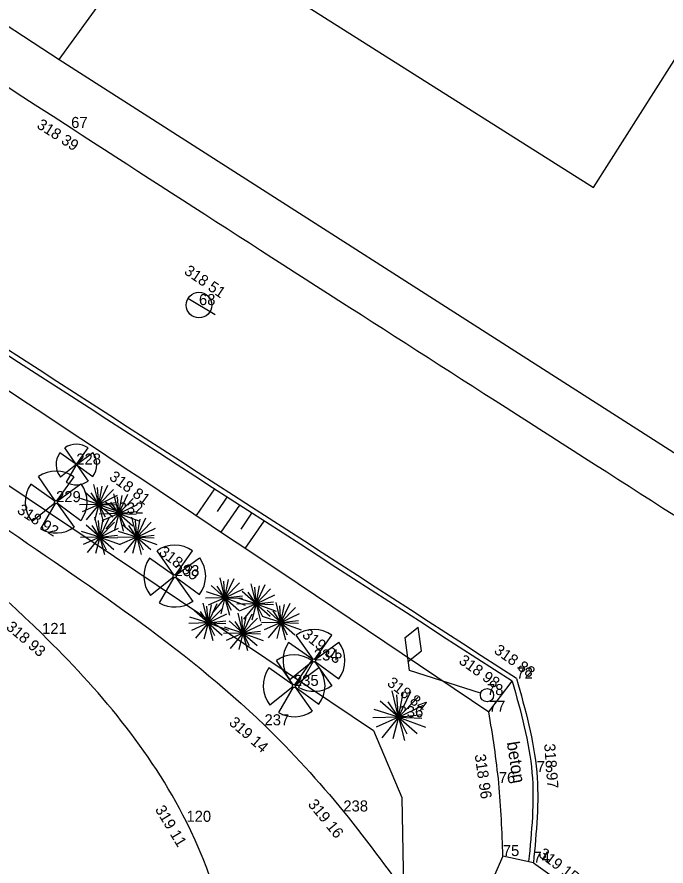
# Model space of a CAD drawing. Extents: x -742884 to -742543, y -1054677 to -1054433.
# Drawn here: x -742681.87 to -742664.25, y -1054523.59 to -1054500.54 of the extents above; entities that cross this region are included whole.
import ezdxf

# ---------------------------------------------------------------- set-up
doc = ezdxf.new("R2010")
doc.units = 0
for name, color, linetype in [('Vrstva 1', 7, 'Continuous'), ('Vrstva 10', 7, 'Continuous'), ('Vrstva 11', 7, 'Continuous'), ('Vrstva 12', 7, 'Continuous'), ('Vrstva 13', 7, 'Continuous'), ('Vrstva 15', 7, 'Continuous'), ('Vrstva 2', 7, 'Continuous'), ('Vrstva 3', 7, 'Continuous'), ('Vrstva 4', 7, 'Continuous'), ('Vrstva 50', 7, 'Continuous'), ('Vrstva 7', 7, 'Continuous')]:
    doc.layers.add(name, color=color, linetype=linetype)

# ---------------------------------------------------------------- blocks, each defined once
blk = doc.blocks.new('Z15')
at = {"layer": 'Vrstva 2'}
for p, q in [((-10, 2), (-8, 6)), ((-10, -2), (-10, 2)), ((-8, 6), (-6, 8)), ((-6, 8), (-2, 10)), ((-2, 10), (2, 10)), ((2, 10), (6, 8)), ((6, 8), (8, 6)), ((8, 6), (10, 2)), ((10, 2), (10, -2)), ((-8, -6), (-10, -2)), ((-6, -8), (-8, -6)), ((-2, -10), (-6, -8)), ((2, -10), (-2, -10)), ((6, -8), (2, -10)), ((8, -6), (6, -8)), ((10, -2), (8, -6))]:
    blk.add_line(p, q, dxfattribs=at)

msp = doc.modelspace()

# ---------------------------------------------------------------- linework, layer by layer
at = {"layer": 'Vrstva 1'}
for p, q in [((-742680.4, -1054503.55), (-742680.4, -1054503.55)), ((-742676.93, -1054508.36), (-742676.93, -1054508.36)), ((-742680.26, -1054512.69), (-742680.26, -1054512.69)), ((-742680.81, -1054513.71), (-742680.81, -1054513.71)), ((-742679.11, -1054514.02), (-742679.11, -1054514.02)), ((-742677.59, -1054515.72), (-742677.59, -1054515.72)), ((-742681.19, -1054517.29), (-742681.19, -1054517.29)), ((-742673.81, -1054518.01), (-742673.81, -1054518.01)), ((-742668.31, -1054518.5), (-742668.31, -1054518.5)), ((-742674.35, -1054518.7), (-742674.35, -1054518.7)), ((-742669.11, -1054518.95), (-742669.11, -1054518.95)), ((-742669.06, -1054519.4), (-742669.06, -1054519.4)), ((-742671.51, -1054519.55), (-742671.51, -1054519.55)), ((-742675.15, -1054519.77), (-742675.15, -1054519.77)), ((-742667.76, -1054521.04), (-742667.76, -1054521.04)), ((-742668.79, -1054521.34), (-742668.79, -1054521.34)), ((-742673.01, -1054522.11), (-742673.01, -1054522.11)), ((-742677.27, -1054522.39), (-742677.27, -1054522.39)), ((-742668.68, -1054523.32), (-742668.68, -1054523.32)), ((-742667.85, -1054523.5), (-742667.85, -1054523.5))]:
    msp.add_line(p, q, dxfattribs=at)
at = {"layer": 'Vrstva 10'}
for p, q in [((-742680.273, -1054512.669), (-742680.573, -1054512.237)), ((-742680.244, -1054512.669), (-742679.94, -1054512.239)), ((-742680.282, -1054512.672), (-742680.708, -1054512.37)), ((-742680.238, -1054512.676), (-742679.815, -1054512.361)), ((-742680.282, -1054512.709), (-742680.687, -1054513.035)), ((-742680.276, -1054512.715), (-742680.536, -1054513.165)), ((-742680.24, -1054512.713), (-742679.939, -1054513.139)), ((-742680.236, -1054512.706), (-742679.815, -1054513.017)), ((-742680.83, -1054513.677), (-742681.287, -1054513.018)), ((-742680.785, -1054513.677), (-742680.322, -1054513.024)), ((-742680.778, -1054513.686), (-742680.134, -1054513.209)), ((-742680.843, -1054513.682), (-742681.495, -1054513.223)), ((-742679.65, -1054513.77), (-742680.025, -1054513.441)), ((-742679.65, -1054513.77), (-742679.783, -1054513.231)), ((-742679.65, -1054513.77), (-742679.684, -1054513.316)), ((-742679.65, -1054513.77), (-742679.402, -1054513.245)), ((-742679.65, -1054513.77), (-742679.557, -1054513.279)), ((-742679.65, -1054513.77), (-742679.254, -1054513.365)), ((-742679.65, -1054513.77), (-742680.149, -1054513.613)), ((-742679.65, -1054513.77), (-742679.861, -1054513.458)), ((-742679.65, -1054513.77), (-742679.142, -1054513.525)), ((-742679.11, -1054514.02), (-742679.243, -1054513.481)), ((-742679.11, -1054514.02), (-742679.144, -1054513.566)), ((-742679.11, -1054514.02), (-742678.862, -1054513.495)), ((-742679.11, -1054514.02), (-742679.017, -1054513.529)), ((-742679.11, -1054514.02), (-742678.714, -1054513.615)), ((-742680.844, -1054513.739), (-742681.463, -1054514.236)), ((-742680.835, -1054513.747), (-742681.232, -1054514.435)), ((-742680.782, -1054513.744), (-742680.321, -1054514.394)), ((-742680.774, -1054513.735), (-742680.134, -1054514.208)), ((-742679.65, -1054513.77), (-742680.176, -1054513.784)), ((-742679.65, -1054513.77), (-742680.105, -1054513.972)), ((-742679.65, -1054513.77), (-742679.995, -1054514.188)), ((-742679.65, -1054513.77), (-742679.765, -1054514.211)), ((-742679.654, -1054513.768), (-742679.654, -1054513.768)), ((-742679.65, -1054513.77), (-742679.173, -1054513.717)), ((-742679.65, -1054513.77), (-742679.65, -1054513.77)), ((-742679.65, -1054513.77), (-742679.479, -1054514.111)), ((-742679.65, -1054513.77), (-742679.1, -1054513.97)), ((-742679.65, -1054513.77), (-742679.173, -1054513.786)), ((-742679.65, -1054513.77), (-742679.269, -1054514.105)), ((-742679.65, -1054513.77), (-742679.528, -1054514.244)), ((-742679.65, -1054513.77), (-742679.65, -1054513.77)), ((-742679.11, -1054514.02), (-742679.609, -1054513.863)), ((-742679.11, -1054514.02), (-742679.485, -1054513.691)), ((-742679.11, -1054514.02), (-742679.321, -1054513.708)), ((-742679.11, -1054514.02), (-742678.602, -1054513.775)), ((-742679.62, -1054514.66), (-742679.753, -1054514.121)), ((-742679.11, -1054514.02), (-742679.636, -1054514.034)), ((-742679.62, -1054514.66), (-742679.372, -1054514.135)), ((-742679.11, -1054514.02), (-742679.565, -1054514.222)), ((-742679.11, -1054514.02), (-742679.455, -1054514.438)), ((-742679.11, -1054514.02), (-742679.225, -1054514.461)), ((-742679.114, -1054514.018), (-742679.114, -1054514.018)), ((-742679.11, -1054514.02), (-742678.633, -1054513.967)), ((-742679.11, -1054514.02), (-742679.11, -1054514.02)), ((-742679.11, -1054514.02), (-742678.939, -1054514.361)), ((-742679.11, -1054514.02), (-742678.56, -1054514.22)), ((-742679.11, -1054514.02), (-742678.633, -1054514.036)), ((-742679.11, -1054514.02), (-742678.729, -1054514.355)), ((-742679.11, -1054514.02), (-742678.988, -1054514.494)), ((-742679.11, -1054514.02), (-742679.11, -1054514.02)), ((-742678.62, -1054514.66), (-742678.753, -1054514.121)), ((-742678.62, -1054514.66), (-742678.372, -1054514.135)), ((-742679.62, -1054514.66), (-742679.995, -1054514.331)), ((-742679.62, -1054514.66), (-742679.831, -1054514.348)), ((-742679.62, -1054514.66), (-742679.654, -1054514.206)), ((-742679.62, -1054514.66), (-742679.527, -1054514.169)), ((-742679.62, -1054514.66), (-742679.224, -1054514.255)), ((-742678.62, -1054514.66), (-742678.995, -1054514.331)), ((-742678.62, -1054514.66), (-742678.831, -1054514.348)), ((-742678.62, -1054514.66), (-742678.654, -1054514.206)), ((-742678.62, -1054514.66), (-742678.527, -1054514.169)), ((-742678.62, -1054514.66), (-742678.224, -1054514.255)), ((-742679.62, -1054514.66), (-742680.119, -1054514.503)), ((-742679.62, -1054514.66), (-742679.112, -1054514.415)), ((-742678.62, -1054514.66), (-742679.119, -1054514.503)), ((-742678.62, -1054514.66), (-742678.112, -1054514.415)), ((-742679.62, -1054514.66), (-742680.146, -1054514.674)), ((-742679.62, -1054514.66), (-742680.075, -1054514.862)), ((-742679.62, -1054514.66), (-742679.965, -1054515.078)), ((-742679.62, -1054514.66), (-742679.735, -1054515.101)), ((-742679.624, -1054514.658), (-742679.624, -1054514.658)), ((-742679.62, -1054514.66), (-742679.143, -1054514.607)), ((-742679.62, -1054514.66), (-742679.62, -1054514.66)), ((-742679.62, -1054514.66), (-742679.449, -1054515.001)), ((-742679.62, -1054514.66), (-742679.07, -1054514.86)), ((-742679.62, -1054514.66), (-742679.143, -1054514.676)), ((-742679.62, -1054514.66), (-742679.239, -1054514.995)), ((-742679.62, -1054514.66), (-742679.498, -1054515.134)), ((-742679.62, -1054514.66), (-742679.62, -1054514.66)), ((-742678.62, -1054514.66), (-742679.146, -1054514.674)), ((-742678.62, -1054514.66), (-742679.075, -1054514.862)), ((-742678.62, -1054514.66), (-742678.965, -1054515.078)), ((-742678.62, -1054514.66), (-742678.735, -1054515.101)), ((-742678.624, -1054514.658), (-742678.624, -1054514.658)), ((-742678.62, -1054514.66), (-742678.143, -1054514.607)), ((-742678.62, -1054514.66), (-742678.62, -1054514.66)), ((-742678.62, -1054514.66), (-742678.449, -1054515.001)), ((-742678.62, -1054514.66), (-742678.07, -1054514.86)), ((-742678.62, -1054514.66), (-742678.143, -1054514.676)), ((-742678.62, -1054514.66), (-742678.239, -1054514.995)), ((-742678.62, -1054514.66), (-742678.498, -1054515.134)), ((-742678.62, -1054514.66), (-742678.62, -1054514.66)), ((-742677.61, -1054515.687), (-742678.067, -1054515.028)), ((-742677.565, -1054515.687), (-742677.102, -1054515.034)), ((-742677.623, -1054515.692), (-742678.275, -1054515.233)), ((-742677.558, -1054515.696), (-742676.914, -1054515.219)), ((-742677.624, -1054515.749), (-742678.243, -1054516.246)), ((-742677.554, -1054515.745), (-742676.914, -1054516.218)), ((-742677.615, -1054515.757), (-742678.012, -1054516.445)), ((-742677.562, -1054515.754), (-742677.101, -1054516.404)), ((-742676.225, -1054516.306), (-742676.6, -1054515.977)), ((-742676.225, -1054516.306), (-742676.358, -1054515.767)), ((-742676.225, -1054516.306), (-742676.259, -1054515.852)), ((-742676.225, -1054516.306), (-742675.977, -1054515.781)), ((-742676.225, -1054516.306), (-742676.132, -1054515.815)), ((-742676.225, -1054516.306), (-742675.829, -1054515.901)), ((-742675.38, -1054516.47), (-742675.513, -1054515.931)), ((-742675.38, -1054516.47), (-742675.132, -1054515.945)), ((-742675.38, -1054516.47), (-742675.287, -1054515.979)), ((-742676.225, -1054516.306), (-742676.724, -1054516.149)), ((-742676.225, -1054516.306), (-742676.436, -1054515.994)), ((-742676.225, -1054516.306), (-742675.717, -1054516.061)), ((-742675.38, -1054516.47), (-742675.755, -1054516.141)), ((-742675.38, -1054516.47), (-742675.591, -1054516.158)), ((-742675.38, -1054516.47), (-742675.414, -1054516.016)), ((-742675.38, -1054516.47), (-742674.984, -1054516.065)), ((-742676.225, -1054516.306), (-742676.751, -1054516.32)), ((-742676.225, -1054516.306), (-742676.68, -1054516.508)), ((-742676.225, -1054516.306), (-742676.57, -1054516.724)), ((-742676.225, -1054516.306), (-742676.34, -1054516.747)), ((-742676.229, -1054516.304), (-742676.229, -1054516.304)), ((-742676.225, -1054516.306), (-742675.748, -1054516.253)), ((-742676.225, -1054516.306), (-742676.225, -1054516.306)), ((-742676.225, -1054516.306), (-742676.054, -1054516.647)), ((-742676.225, -1054516.306), (-742675.675, -1054516.506)), ((-742676.225, -1054516.306), (-742675.748, -1054516.322)), ((-742676.225, -1054516.306), (-742675.844, -1054516.641)), ((-742676.225, -1054516.306), (-742676.103, -1054516.78)), ((-742676.225, -1054516.306), (-742676.225, -1054516.306)), ((-742675.38, -1054516.47), (-742675.879, -1054516.313)), ((-742675.38, -1054516.47), (-742674.872, -1054516.225)), ((-742675.38, -1054516.47), (-742674.903, -1054516.417)), ((-742674.705, -1054516.976), (-742674.838, -1054516.437)), ((-742676.68, -1054516.99), (-742677.055, -1054516.661)), ((-742676.68, -1054516.99), (-742676.813, -1054516.451)), ((-742676.68, -1054516.99), (-742676.714, -1054516.536)), ((-742676.68, -1054516.99), (-742676.432, -1054516.465)), ((-742676.68, -1054516.99), (-742676.587, -1054516.499)), ((-742676.68, -1054516.99), (-742676.284, -1054516.585)), ((-742675.38, -1054516.47), (-742675.906, -1054516.484)), ((-742675.38, -1054516.47), (-742675.835, -1054516.672)), ((-742675.38, -1054516.47), (-742675.725, -1054516.888)), ((-742675.38, -1054516.47), (-742675.495, -1054516.911)), ((-742675.384, -1054516.468), (-742675.384, -1054516.468)), ((-742675.38, -1054516.47), (-742675.38, -1054516.47)), ((-742675.38, -1054516.47), (-742675.209, -1054516.811)), ((-742675.38, -1054516.47), (-742674.83, -1054516.67)), ((-742675.38, -1054516.47), (-742674.903, -1054516.486)), ((-742675.38, -1054516.47), (-742674.999, -1054516.805)), ((-742675.38, -1054516.47), (-742675.258, -1054516.944)), ((-742675.38, -1054516.47), (-742675.38, -1054516.47)), ((-742674.705, -1054516.976), (-742675.08, -1054516.647)), ((-742674.705, -1054516.976), (-742674.916, -1054516.664)), ((-742674.705, -1054516.976), (-742674.739, -1054516.522)), ((-742674.705, -1054516.976), (-742674.457, -1054516.451)), ((-742674.705, -1054516.976), (-742674.612, -1054516.485)), ((-742674.705, -1054516.976), (-742674.309, -1054516.571)), ((-742676.68, -1054516.99), (-742677.179, -1054516.833)), ((-742676.68, -1054516.99), (-742676.891, -1054516.678)), ((-742676.68, -1054516.99), (-742676.172, -1054516.745)), ((-742675.735, -1054517.266), (-742675.868, -1054516.727)), ((-742675.735, -1054517.266), (-742675.769, -1054516.812)), ((-742675.735, -1054517.266), (-742675.487, -1054516.741)), ((-742675.735, -1054517.266), (-742675.642, -1054516.775)), ((-742675.735, -1054517.266), (-742675.339, -1054516.861)), ((-742674.705, -1054516.976), (-742675.204, -1054516.819)), ((-742674.705, -1054516.976), (-742674.197, -1054516.731)), ((-742676.68, -1054516.99), (-742677.206, -1054517.004)), ((-742676.68, -1054516.99), (-742677.135, -1054517.192)), ((-742676.68, -1054516.99), (-742677.025, -1054517.408)), ((-742676.68, -1054516.99), (-742676.795, -1054517.431)), ((-742676.684, -1054516.988), (-742676.684, -1054516.988)), ((-742676.68, -1054516.99), (-742676.203, -1054516.937)), ((-742676.68, -1054516.99), (-742676.68, -1054516.99)), ((-742676.68, -1054516.99), (-742676.509, -1054517.331)), ((-742676.68, -1054516.99), (-742676.13, -1054517.19)), ((-742676.68, -1054516.99), (-742676.203, -1054517.006)), ((-742676.68, -1054516.99), (-742676.299, -1054517.325)), ((-742676.68, -1054516.99), (-742676.558, -1054517.464)), ((-742676.68, -1054516.99), (-742676.68, -1054516.99)), ((-742675.735, -1054517.266), (-742676.234, -1054517.109)), ((-742675.735, -1054517.266), (-742676.11, -1054516.937)), ((-742675.735, -1054517.266), (-742675.946, -1054516.954)), ((-742675.735, -1054517.266), (-742675.227, -1054517.021)), ((-742674.705, -1054516.976), (-742675.231, -1054516.99)), ((-742674.705, -1054516.976), (-742675.16, -1054517.178)), ((-742674.705, -1054516.976), (-742675.05, -1054517.394)), ((-742674.705, -1054516.976), (-742674.82, -1054517.417)), ((-742674.709, -1054516.974), (-742674.709, -1054516.974)), ((-742674.705, -1054516.976), (-742674.228, -1054516.923)), ((-742674.705, -1054516.976), (-742674.705, -1054516.976)), ((-742674.705, -1054516.976), (-742674.534, -1054517.317)), ((-742674.705, -1054516.976), (-742674.155, -1054517.176)), ((-742674.705, -1054516.976), (-742674.228, -1054516.992)), ((-742674.705, -1054516.976), (-742674.324, -1054517.311)), ((-742674.705, -1054516.976), (-742674.583, -1054517.45)), ((-742674.705, -1054516.976), (-742674.705, -1054516.976)), ((-742675.735, -1054517.266), (-742676.261, -1054517.28)), ((-742675.735, -1054517.266), (-742676.19, -1054517.468)), ((-742675.735, -1054517.266), (-742676.08, -1054517.684)), ((-742675.735, -1054517.266), (-742675.85, -1054517.707)), ((-742675.739, -1054517.264), (-742675.739, -1054517.264)), ((-742675.735, -1054517.266), (-742675.258, -1054517.213)), ((-742675.735, -1054517.266), (-742675.735, -1054517.266)), ((-742675.735, -1054517.266), (-742675.564, -1054517.607)), ((-742675.735, -1054517.266), (-742675.185, -1054517.466)), ((-742675.735, -1054517.266), (-742675.258, -1054517.282)), ((-742675.735, -1054517.266), (-742675.354, -1054517.601)), ((-742675.735, -1054517.266), (-742675.613, -1054517.74)), ((-742675.735, -1054517.266), (-742675.735, -1054517.266)), ((-742673.83, -1054517.977), (-742674.287, -1054517.318)), ((-742673.785, -1054517.977), (-742673.322, -1054517.324)), ((-742673.843, -1054517.982), (-742674.495, -1054517.523)), ((-742673.778, -1054517.986), (-742673.134, -1054517.509)), ((-742674.37, -1054518.667), (-742674.827, -1054518.008)), ((-742673.844, -1054518.039), (-742674.463, -1054518.536)), ((-742674.325, -1054518.667), (-742673.862, -1054518.014)), ((-742673.835, -1054518.047), (-742674.232, -1054518.735)), ((-742673.782, -1054518.044), (-742673.321, -1054518.694)), ((-742673.774, -1054518.035), (-742673.134, -1054518.508)), ((-742674.383, -1054518.672), (-742675.035, -1054518.213)), ((-742674.318, -1054518.676), (-742673.674, -1054518.199)), ((-742674.384, -1054518.729), (-742675.003, -1054519.226)), ((-742674.375, -1054518.737), (-742674.772, -1054519.425)), ((-742674.322, -1054518.734), (-742673.861, -1054519.384)), ((-742674.314, -1054518.725), (-742673.674, -1054519.198)), ((-742671.51, -1054519.55), (-742671.687, -1054518.833)), ((-742671.51, -1054519.55), (-742671.555, -1054518.946)), ((-742671.51, -1054519.55), (-742671.18, -1054518.85)), ((-742671.51, -1054519.55), (-742671.387, -1054518.896)), ((-742671.51, -1054519.55), (-742672.011, -1054519.112)), ((-742671.51, -1054519.55), (-742671.792, -1054519.135)), ((-742671.51, -1054519.55), (-742670.983, -1054519.01)), ((-742671.51, -1054519.55), (-742672.175, -1054519.341)), ((-742671.51, -1054519.55), (-742670.834, -1054519.223)), ((-742671.51, -1054519.55), (-742672.211, -1054519.569)), ((-742671.51, -1054519.55), (-742672.116, -1054519.818)), ((-742671.51, -1054519.55), (-742671.969, -1054520.106)), ((-742671.51, -1054519.55), (-742671.664, -1054520.136)), ((-742671.516, -1054519.548), (-742671.516, -1054519.548)), ((-742671.514, -1054519.548), (-742671.514, -1054519.548)), ((-742671.51, -1054519.55), (-742670.875, -1054519.48)), ((-742671.51, -1054519.55), (-742671.51, -1054519.55)), ((-742671.51, -1054519.55), (-742671.51, -1054519.55)), ((-742671.51, -1054519.55), (-742671.51, -1054519.55)), ((-742671.51, -1054519.55), (-742671.284, -1054520.004)), ((-742671.51, -1054519.55), (-742670.779, -1054519.816)), ((-742671.51, -1054519.55), (-742670.875, -1054519.572)), ((-742671.51, -1054519.55), (-742671.003, -1054519.995)), ((-742671.51, -1054519.55), (-742671.349, -1054520.18)), ((-742671.51, -1054519.55), (-742671.51, -1054519.55))]:
    msp.add_line(p, q, dxfattribs=at)
for centre, radius, start, end in [((-742680.258, -1054512.689), 0.551, 54.7465, 124.8105), ((-742680.259, -1054512.687), 0.551, 144.8767, 218.9336), ((-742680.258, -1054512.689), 0.551, 323.4756, 36.2971), ((-742680.808, -1054513.708), 0.84, 54.7465, 124.8105), ((-742680.258, -1054512.689), 0.551, 239.6151, 305.4552), ((-742680.808, -1054513.708), 0.84, 323.4756, 36.2971), ((-742680.809, -1054513.706), 0.84, 144.8767, 218.9336), ((-742680.808, -1054513.708), 0.84, 239.6151, 305.4552), ((-742677.588, -1054515.718), 0.84, 54.7465, 124.8105), ((-742677.589, -1054515.716), 0.84, 144.8767, 218.9336), ((-742677.588, -1054515.718), 0.84, 323.4756, 36.2971), ((-742677.588, -1054515.718), 0.84, 239.6151, 305.4552), ((-742673.808, -1054518.008), 0.84, 54.7465, 124.8105), ((-742673.809, -1054518.006), 0.84, 144.8767, 218.9336), ((-742673.808, -1054518.008), 0.84, 323.4756, 36.2971), ((-742674.348, -1054518.698), 0.84, 54.7465, 124.8105), ((-742674.349, -1054518.696), 0.84, 144.8767, 218.9336), ((-742674.348, -1054518.698), 0.84, 323.4756, 36.2971), ((-742673.808, -1054518.008), 0.84, 239.6151, 305.4552), ((-742674.348, -1054518.698), 0.84, 239.6151, 305.4552)]:
    msp.add_arc(centre, radius, start, end, dxfattribs=at)
at = {"layer": 'Vrstva 11'}
for p, q in [((-742676.51, -1054513.352), (-742677.009, -1054514.076)), ((-742676.17, -1054513.571), (-742676.439, -1054513.961)), ((-742675.832, -1054513.789), (-742676.337, -1054514.526)), ((-742675.789, -1054514.443), (-742675.492, -1054514.009)), ((-742675.673, -1054514.971), (-742675.159, -1054514.224))]:
    msp.add_line(p, q, dxfattribs=at)
for points in [[(-742776.7, -1054542.68), (-742764.01, -1054527.79), (-742751.11, -1054512.75), (-742737.61, -1054496.47), (-742726.42, -1054483.98), (-742725.9, -1054484.03), (-742714, -1054491.86), (-742704.819, -1054497.481), (-742700.94, -1054500.269), (-742696.44, -1054503.39), (-742688.83, -1054509.5), (-742682.54, -1054514.17), (-742675.15, -1054519.77), (-742673.01, -1054522.11), (-742671.05, -1054524.7)], [(-742696.97, -1054500.991), (-742684.16, -1054509.32), (-742669.06, -1054519.4)], [(-742641.45, -1054542), (-742646.08, -1054542.32), (-742650.28, -1054545.1), (-742653.63, -1054549.14), (-742658.66, -1054557.13), (-742664.13, -1054565.84), (-742667.81, -1054569.62), (-742669.76, -1054570.07), (-742674.4, -1054567.88), (-742684.66, -1054562.03), (-742693.02, -1054556.88), (-742694.43, -1054554.37), (-742693.99, -1054552.67), (-742684.52, -1054539.64), (-742677.51, -1054529.95), (-742676.26, -1054526.54), (-742677.27, -1054522.39), (-742681.19, -1054517.29), (-742689.28, -1054510.73), (-742697.86, -1054505.14), (-742704.02, -1054502.75), (-742713.11, -1054501.07), (-742723.98, -1054503.51), (-742736.77, -1054510.1), (-742745.39, -1054515.75), (-742752.81, -1054521.82), (-742762.72, -1054531.38), (-742770.54, -1054539.36), (-742775.54, -1054544.64)]]:
    msp.add_spline(points, degree=3, dxfattribs=at)
at = {"layer": 'Vrstva 12'}
for points in [[(-742671.329, -1054517.386), (-742670.979, -1054517.104)], [(-742670.892, -1054517.745), (-742670.979, -1054517.104)], [(-742671.21, -1054518.28), (-742671.329, -1054517.386)], [(-742671.243, -1054518.028), (-742670.892, -1054517.745)], [(-742669.283, -1054518.895), (-742671.21, -1054518.28)]]:
    msp.add_lwpolyline(points, dxfattribs=at)
msp.add_circle((-742669.11, -1054518.95), 0.18, dxfattribs=at)
at = {"layer": 'Vrstva 13'}
for p, q in [((-742669.06, -1054519.4), (-742668.427, -1054518.573)), ((-742668.68, -1054523.32), (-742670, -1054526.35)), ((-742667.85, -1054523.5), (-742668.68, -1054523.32))]:
    msp.add_line(p, q, dxfattribs=at)
msp.add_spline([(-742668.68, -1054523.32), (-742668.79, -1054521.34), (-742669.06, -1054519.4)], degree=3, dxfattribs=at)
at = {"layer": 'Vrstva 4'}
msp.add_lwpolyline([(-742667.85, -1054523.5), (-742664.52, -1054525.88), (-742664.71, -1054526.14), (-742664.786, -1054526.246)], dxfattribs=at)
for points in [[(-742718.8, -1054478.84), (-742709.4, -1054484.88), (-742695.99, -1054493.43), (-742680.4, -1054503.55), (-742661.01, -1054516), (-742635.78, -1054532.31)], [(-742668.427, -1054518.574), (-742683.74, -1054508.68), (-742696.59, -1054500.4), (-742699.13, -1054498.77), (-742713.15, -1054489.73), (-742724.623, -1054482.289)], [(-742668.31, -1054518.5), (-742683.67, -1054508.57), (-742699.06, -1054498.66), (-742713.08, -1054489.62), (-742724.57, -1054482.17)], [(-742668.31, -1054518.5), (-742667.76, -1054521.04), (-742667.85, -1054523.5)], [(-742668.427, -1054518.573), (-742667.889, -1054521.052), (-742667.979, -1054523.472)]]:
    msp.add_spline(points, degree=3, dxfattribs=at)
at = {"layer": 'Vrstva 50'}
for p, q in [((-742680.73, -1054501.69), (-742661.786, -1054475.637)), ((-742697.33, -1054490.84), (-742680.73, -1054501.69)), ((-742680.73, -1054501.69), (-742663.94, -1054512.43))]:
    msp.add_line(p, q, dxfattribs=at)
for points in [[(-742657.61, -1054484.93), (-742655.81, -1054482.15), (-742660.56, -1054479.21), (-742665.7, -1054487.1), (-742666.25, -1054486.74), (-742674.65, -1054499.83), (-742666.22, -1054505.17), (-742661.11, -1054497.12), (-742664.22, -1054495.12), (-742657.61, -1054484.93)], [(-742724.95, -1054484.46), (-742672.19, -1054519.91), (-742671.42, -1054521.73), (-742671.38, -1054524.18), (-742670.45, -1054526.06)]]:
    msp.add_lwpolyline(points, dxfattribs=at)
at = {"layer": 'Vrstva 7'}
msp.add_line((-742676.487, -1054508.624), (-742677.229, -1054508.182), dxfattribs=at)
msp.add_circle((-742676.93, -1054508.36), 0.347, dxfattribs=at)

# ---------------------------------------------------------------- block references
at = {"layer": 'Vrstva 10'}
for p, xscale, yscale, rotation in [((-742680.26, -1054512.69), 0.002754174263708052, 0.002754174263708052, -30.671756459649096), ((-742680.81, -1054513.71), 0.004197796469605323, 0.004197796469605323, -30.671756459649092), ((-742677.59, -1054515.72), 0.004197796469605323, 0.004197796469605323, -30.671756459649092), ((-742673.81, -1054518.01), 0.004197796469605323, 0.004197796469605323, -30.671756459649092), ((-742674.35, -1054518.7), 0.004197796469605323, 0.004197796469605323, -30.671756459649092)]:
    msp.add_blockref('Z15', p, dxfattribs=dict(at, xscale=xscale, yscale=yscale, rotation=rotation))

# ---------------------------------------------------------------- texts
at = {"layer": 'Vrstva 15'}
msp.add_text('beton', height=0.3407, rotation=278.6913, dxfattribs=at).set_placement((-742668.574, -1054520.233))
at = {"layer": 'Vrstva 2'}
for s, p in [('67', (-742680.4, -1054503.55)), ('68', (-742676.93, -1054508.36)), ('228', (-742680.26, -1054512.69)), ('229', (-742680.81, -1054513.71)), ('232', (-742679.11, -1054514.02)), ('233', (-742677.59, -1054515.72)), ('121', (-742681.19, -1054517.29)), ('234', (-742673.81, -1054518.01)), ('72', (-742668.31, -1054518.5)), ('235', (-742674.35, -1054518.7)), ('78', (-742669.11, -1054518.95)), ('77', (-742669.06, -1054519.4)), ('236', (-742671.51, -1054519.55)), ('237', (-742675.15, -1054519.77)), ('73', (-742667.76, -1054521.04)), ('76', (-742668.79, -1054521.34)), ('238', (-742673.01, -1054522.11)), ('120', (-742677.27, -1054522.39)), ('75', (-742668.68, -1054523.32)), ('74', (-742667.85, -1054523.5))]:
    msp.add_text(s, height=0.3, dxfattribs=at).set_placement(p)
at = {"layer": 'Vrstva 3'}
for s, rotation, p in [('318 39 ', 327.6477, (-742681.357, -1054503.533)), ('318 51 ', 325.7884, (-742677.355, -1054507.495)), ('318 81 ', 323.9953, (-742679.389, -1054513.078)), ('318 92 ', 326.5369, (-742681.893, -1054513.985)), ('318 99 ', 322.5946, (-742678.042, -1054515.116)), ('318 93 ', 319.7007, (-742682.189, -1054517.139)), ('319 03 ', 321.1322, (-742674.152, -1054517.349)), ('318 88 ', 324.9391, (-742668.943, -1054517.79)), ('318 98 ', 324.698, (-742669.899, -1054518.07)), ('318 84 ', 322.125, (-742671.847, -1054518.666)), ('319 14 ', 318.8879, (-742676.137, -1054519.73)), ('318 97 ', 274.3461, (-742667.559, -1054520.276)), ('318 96 ', 278.2559, (-742669.447, -1054520.571)), ('319 11 ', 301.0436, (-742678.133, -1054522.052)), ('319 16 ', 309.4725, (-742673.99, -1054521.921)), ('319 15 ', 322.8485, (-742667.736, -1054523.311))]:
    msp.add_text(s, height=0.3, rotation=rotation, dxfattribs=at).set_placement(p)

doc.saveas('drawing.dxf')
